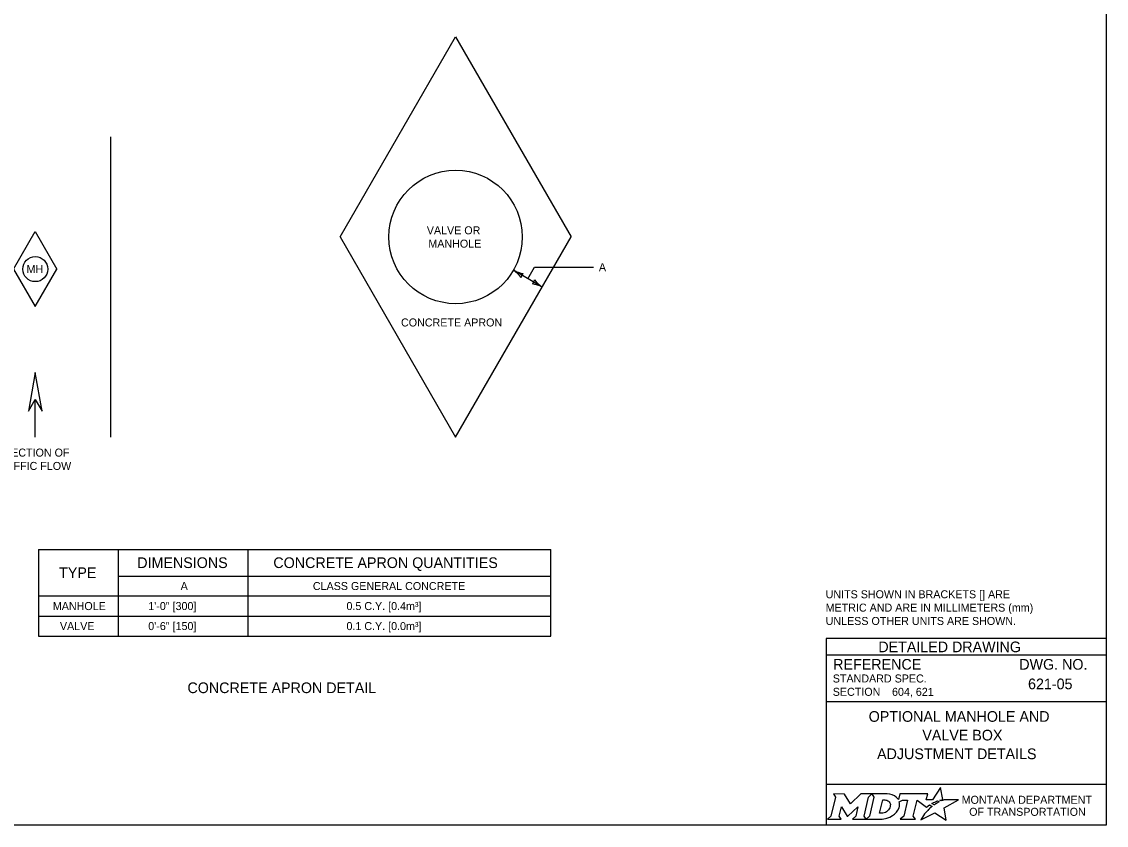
# Model space of a CAD drawing. Extents: x 49991.4 to 50021, y 49987.6 to 50011.4.
# Drawn here: x 50008.62 to 50016.75, y 49987.8 to 49993.82 of the extents above; entities that cross this region are included whole.
import ezdxf

# ---------------------------------------------------------------- set-up
doc = ezdxf.new("R2010")
doc.units = 0
for name, color, linetype in [('Default', 7, 'Continuous'), ('Level 1', 7, 'Continuous'), ('Level 2', 7, 'Continuous'), ('Level 3', 7, 'Continuous'), ('Level 5', 7, 'Continuous')]:
    doc.layers.add(name, color=color, linetype=linetype)

msp = doc.modelspace()

# ---------------------------------------------------------------- linework, layer by layer
at = {"layer": 'Default'}
for points in [[(50015.5126, 49987.9811), (50015.5023, 49987.9867), (50015.5139, 49987.9895), (50015.5255, 49987.9915), (50015.5081, 49988.0816), (50015.4486, 49987.9903), (50015.4013, 49987.9896), (50015.4116, 49988.0337), (50015.2024, 49988.0338), (50015.1923, 49987.9913), (50015.1865, 49987.9996)], [(50014.7056, 49988.0338), (50014.7197, 49988.0104), (50014.6862, 49987.8671), (50014.6605, 49987.8446), (50014.7621, 49987.8446), (50014.7486, 49987.8674), (50014.7648, 49987.9375), (50014.8085, 49987.8685), (50014.8138, 49987.8685), (50014.8889, 49987.938), (50014.8725, 49987.8669), (50014.8478, 49987.8449), (50014.9494, 49987.8449), (50014.9356, 49987.8682), (50014.9688, 49988.0106)], [(50014.9688, 49988.0106), (50014.9941, 49988.0338), (50014.9117, 49988.0338), (50014.8321, 49987.9608), (50014.7876, 49988.0335), (50014.7056, 49988.0338)], [(50015.1077, 49988.0338), (50014.9941, 49988.0338), (50015.0088, 49988.0109), (50014.9749, 49987.8671), (50014.9494, 49987.8449), (50015.06, 49987.8449)], [(50015.1317, 49987.9471), (50015.1305, 49987.939), (50015.1273, 49987.9297), (50015.1231, 49987.9215), (50015.1175, 49987.914), (50015.111, 49987.9071), (50015.1031, 49987.9008), (50015.0948, 49987.8961), (50015.0857, 49987.8922), (50015.0766, 49987.8899), (50015.0674, 49987.889), (50015.0515, 49987.889), (50015.0751, 49987.989), (50015.0911, 49987.989), (50015.0987, 49987.9884), (50015.1063, 49987.9865), (50015.1129, 49987.9835), (50015.119, 49987.9793), (50015.1238, 49987.9743), (50015.1275, 49987.9683), (50015.1302, 49987.9621), (50015.1318, 49987.9547), (50015.1318, 49987.9517), (50015.1317, 49987.9471)], [(50015.1991, 49987.9747), (50015.2237, 49987.9878), (50015.2606, 49987.9878), (50015.232, 49987.8673), (50015.2045, 49987.8446), (50015.3207, 49987.8446), (50015.3037, 49987.8675), (50015.3319, 49987.9877), (50015.4032, 49987.936), (50015.4243, 49987.9511), (50015.444, 49987.9402)], [(50015.3882, 49987.8843), (50015.3729, 49987.8599), (50015.3682, 49987.8524), (50015.3624, 49987.8438), (50015.3601, 49987.8395), (50015.4654, 49987.8926), (50015.5493, 49987.8375), (50015.5362, 49987.9302), (50015.6431, 49987.9886), (50015.5938, 49987.9894), (50015.5637, 49987.9898), (50015.5429, 49987.9901), (50015.5361, 49987.9886), (50015.5312, 49987.9874), (50015.5228, 49987.9851), (50015.5126, 49987.9811)], [(50015.4622, 49987.9535), (50015.4598, 49987.9518), (50015.4415, 49987.9614), (50015.4518, 49987.9671), (50015.4559, 49987.9693), (50015.4645, 49987.9733), (50015.4702, 49987.9759), (50015.4781, 49987.9789), (50015.4854, 49987.9816), (50015.4972, 49987.9742), (50015.4932, 49987.9721), (50015.4886, 49987.9696), (50015.4844, 49987.9674), (50015.4794, 49987.9645), (50015.4775, 49987.9634), (50015.4748, 49987.9618), (50015.4723, 49987.9604), (50015.47, 49987.9588), (50015.4674, 49987.957), (50015.4647, 49987.9552), (50015.4622, 49987.9535)], [(50015.4021, 49987.9004), (50015.4021, 49987.9004)], [(50015.1057, 49987.8522), (50015.1141, 49987.8548), (50015.1271, 49987.8602), (50015.1475, 49987.8712)]]:
    msp.add_lwpolyline(points, dxfattribs=at)
for centre, radius, start, end in [((50015.0868, 49987.9727), 0.1183, 300.91025, 339.13831), ((50015.1308, 49987.9554), 0.0709, 339.53292, 15.85821)]:
    msp.add_arc(centre, radius, start, end, dxfattribs=at)
for centre, major_axis, ratio, start_param, end_param in [((50015.1056, 49987.9864), (0.0834, -0.0037), 0.568097, 0.61298, 1.570796), ((50015.1612, 49987.9937), (0.0361, -0.0295), 0.469099, 1.225588, 1.570796), ((50015.3952, 49987.8923), (-0.00694, -0.00806), 0.008222, 0, 3.137361), ((50015.4119, 49987.9106), (-0.0098, -0.0102), 0.016458, 3.141593, 6.279097), ((50015.4329, 49987.9305), (-0.0112, -0.0097), 0.021651, 3.157348, 6.283185), ((50015.0603, 49987.9932), (0, 0.1484), 0.987302, 3.139398, 3.456847)]:
    msp.add_ellipse(centre, major_axis=major_axis, ratio=ratio, start_param=start_param, end_param=end_param, dxfattribs=at)
at = {"layer": 'Level 1'}
for p, q in [((50011.0079, 49992.2088), (50011.8739, 49993.7088)), ((50011.8739, 49993.7088), (50012.7399, 49992.2088)), ((50009.287, 49992.9588), (50009.287, 49990.7088)), ((50008.5621, 49991.9677), (50008.7245, 49992.249)), ((50008.7245, 49992.249), (50008.8869, 49991.9677)), ((50011.0079, 49992.2088), (50011.8739, 49990.7088)), ((50011.8739, 49990.7088), (50012.7399, 49992.2088)), ((50008.5621, 49991.9677), (50008.7245, 49991.6865)), ((50008.7245, 49991.6865), (50008.8869, 49991.9677)), ((50008.7246, 49990.7088), (50008.7246, 49990.9918))]:
    msp.add_line(p, q, dxfattribs=at)
for points in [[(49999.3835, 49998.9992), (50016.7501, 49998.9992), (50016.7501, 49987.7988), (49999.3835, 49987.7988)], [(50008.7759, 49990.903), (50008.7246, 49991.194), (50008.6731, 49990.903), (50008.7246, 49990.9918)]]:
    msp.add_lwpolyline(points, close=True, dxfattribs=at)
for centre, radius in [((50011.8739, 49992.2088), 0.5), ((50008.7245, 49991.9677), 0.0938)]:
    msp.add_circle(centre, radius, dxfattribs=at)
at = {"layer": 'Level 2'}
for p, q in [((50008.7484, 49989.8673), (50012.5865, 49989.8673)), ((50008.7484, 49989.8673), (50008.7484, 49989.2173)), ((50009.3469, 49989.2173), (50009.3469, 49989.8673)), ((50010.3196, 49989.2173), (50010.3196, 49989.8673)), ((50012.5865, 49989.2173), (50012.5865, 49989.8673)), ((50009.3469, 49989.6673), (50012.5865, 49989.6673)), ((50012.5865, 49989.5173), (50008.7484, 49989.5173)), ((50008.7484, 49989.3673), (50012.5865, 49989.3673)), ((50008.7484, 49989.2173), (50012.5865, 49989.2173))]:
    msp.add_line(p, q, dxfattribs=at)
at = {"layer": 'Level 3'}
for p, q in [((50012.4152, 49991.8963), (50012.4646, 49991.982)), ((50012.4646, 49991.982), (50012.9079, 49991.982)), ((50012.5234, 49991.8338), (50012.3069, 49991.9588))]:
    msp.add_line(p, q, dxfattribs=at)
for centre, radius, start, end in [((50012.41, 49992.1558), 0.2223, 242.36048, 262.54399), ((50012.1806, 49991.763), 0.233, 37.92284, 57.17269), ((50012.4179, 49991.8947), 0.0548, 132.13882, 167.86118), ((50012.4124, 49991.8979), 0.0548, 312.13882, 347.86118), ((50012.6424, 49992.0216), 0.2223, 217.45601, 237.63952), ((50012.417, 49991.6265), 0.233, 62.82731, 82.07716)]:
    msp.add_arc(centre, radius, start, end, dxfattribs=at)
at = {"layer": 'Level 5'}
for p, q in [((50016.7501, 49989.1988), (50014.6501, 49989.1988)), ((50014.6501, 49989.1988), (50014.6501, 49987.7988)), ((50016.7501, 49989.0738), (50014.6501, 49989.0738)), ((50015.1444, 49988.7993), (50015.1444, 49988.7993)), ((50016.3862, 49988.8587), (50016.3862, 49988.8587)), ((50016.7501, 49988.7238), (50014.6501, 49988.7238)), ((50015.7001, 49988.4747), (50015.7001, 49988.4747)), ((50016.7501, 49988.1057), (50014.6501, 49988.1057))]:
    msp.add_line(p, q, dxfattribs=at)

# ---------------------------------------------------------------- texts
at = {"layer": 'Default'}
for s, p in [('MONTANA DEPARTMENT', (50015.6663, 49987.96)), ('OF TRANSPORTATION', (50015.7225, 49987.87))]:
    msp.add_text(s, height=0.06, dxfattribs=at).set_placement(p)
at = {"layer": 'Level 2'}
for s, height, p in [('VALVE OR ', 0.06, (50011.6583, 49992.2288)), ('MANHOLE', 0.06, (50011.6699, 49992.1288)), ('MH', 0.06, (50008.6594, 49991.9377)), ('A', 0.06, (50012.9479, 49991.952)), ('CONCRETE APRON', 0.06, (50011.4652, 49991.538)), ('DIRECTION OF', 0.06, (50008.4057, 49990.5626)), ('TRAFFIC FLOW', 0.06, (50008.401, 49990.4626)), ('DIMENSIONS', 0.08, (50009.4887, 49989.7273)), ('CONCRETE APRON QUANTITIES', 0.08, (50010.5085, 49989.7273)), ('TYPE', 0.08, (50008.9031, 49989.6523)), ('A', 0.06, (50009.8136, 49989.5623)), ('CLASS GENERAL CONCRETE', 0.06, (50010.8046, 49989.5623)), ('UNITS SHOWN IN BRACKETS [] ARE ', 0.06, (50014.6469, 49989.5006)), ('MANHOLE', 0.06, (50008.8561, 49989.4123)), ('1\'-0" [300]', 0.06, (50009.5712, 49989.4123)), ('0.5 C.Y. [0.4m³]', 0.06, (50011.0564, 49989.4123)), ('METRIC AND ARE IN MILLIMETERS (mm) ', 0.06, (50014.6469, 49989.4006)), ('UNLESS OTHER UNITS ARE SHOWN.', 0.06, (50014.6469, 49989.3006)), ('VALVE', 0.06, (50008.9093, 49989.2623)), ('0\'-6" [150]', 0.06, (50009.5712, 49989.2623)), ('0.1 C.Y. [0.0m³]', 0.06, (50011.0564, 49989.2623)), ('621-05', 0.08, (50016.1636, 49988.8187)), ('CONCRETE APRON DETAIL', 0.08, (50009.8648, 49988.7897)), ('604, 621', 0.06, (50015.1444, 49988.7693)), ('OPTIONAL MANHOLE AND', 0.08, (50014.9695, 49988.5747)), ('VALVE BOX', 0.08, (50015.3713, 49988.4347)), ('ADJUSTMENT DETAILS', 0.08, (50015.0323, 49988.2947))]:
    msp.add_text(s, height=height, dxfattribs=at).set_placement(p)
at = {"layer": 'Level 5'}
for s, height, p in [('DETAILED DRAWING', 0.0799, (50015.0418, 49989.0963)), ('REFERENCE', 0.08, (50014.7037, 49988.9654)), ('DWG. NO.', 0.08, (50016.0979, 49988.9654)), ('STANDARD SPEC.', 0.06, (50014.7004, 49988.8694)), ('SECTION', 0.06, (50014.7004, 49988.7694))]:
    msp.add_text(s, height=height, dxfattribs=at).set_placement(p)

doc.saveas('drawing.dxf')
